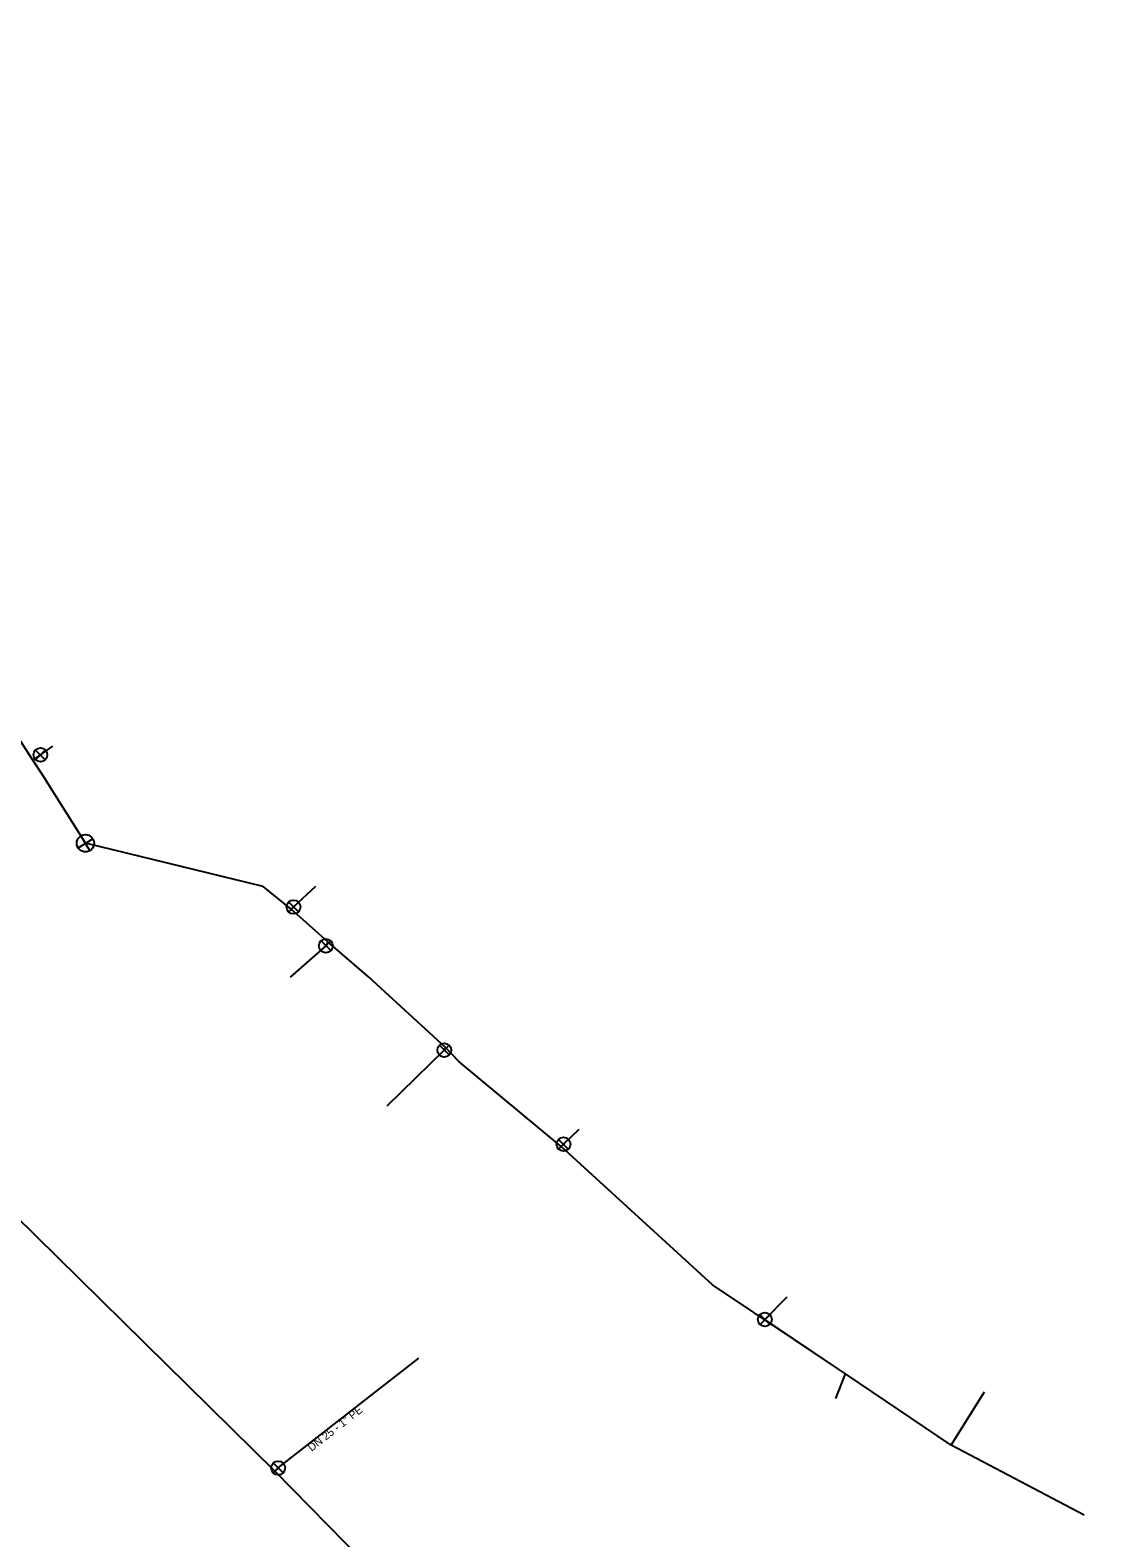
# Model space of a CAD drawing. Extents: x -484785 to -484462, y -1128039 to -1127627.
# Drawn here: x -484646.3 to -484583.5, y -1127805.6 to -1127718.2 of the extents above; entities that cross this region are included whole.
import ezdxf

# ---------------------------------------------------------------- set-up
doc = ezdxf.new("R2010")
doc.units = 0
for name, color, linetype in [('_pripojka_prevzato_z_dokumentace_', 7, 'Continuous'), ('_pripojka_priblizne_', 7, 'Continuous'), ('_voda_smvak_prevzato_z_dokumentace_', 7, 'Continuous'), ('Default', 7, 'Continuous'), ('MoLevel 27', 7, 'Continuous'), ('MoLevel 53', 7, 'Continuous'), ('MoLevel 55', 7, 'Continuous')]:
    doc.layers.add(name, color=color, linetype=linetype)

# ---------------------------------------------------------------- blocks, each defined once
blk = doc.blocks.new('_uzaver_')
at = {"layer": 'Default'}
for p, q in [((-0.000035, -0.000035), (0.000035, 0.000035)), ((0.000035, -0.000035), (-0.000035, 0.000035))]:
    blk.add_line(p, q, dxfattribs=at)
for radius in [0.00005, 0.0000025]:
    blk.add_circle((0, 0), radius, dxfattribs=at)
blk = doc.blocks.new('_uzaver_pripojka_')
at = {"layer": 'Default'}
for p, q in [((-0.000035, -0.000035), (0.000035, 0.000035)), ((0.000035, -0.000035), (-0.000035, 0.000035))]:
    blk.add_line(p, q, dxfattribs=at)
for radius in [0.00005, 0.0000025]:
    blk.add_circle((0, 0), radius, dxfattribs=at)

msp = doc.modelspace()

# ---------------------------------------------------------------- linework, layer by layer
at = {"layer": '_pripojka_prevzato_z_dokumentace_'}
for points in [[(-484646.121, -1127760.523), (-484645.69, -1127760.22), (-484644.967, -1127759.711)], [(-484631.161, -1127769.165), (-484631.03, -1127769.03), (-484629.732, -1127767.818)], [(-484629.046, -1127771.058), (-484629.16, -1127771.28), (-484631.218, -1127773.099)], [(-484622.225, -1127777.17), (-484622.3, -1127777.32), (-484625.631, -1127780.569)], [(-484615.535, -1127782.894), (-484615.4, -1127782.77), (-484614.496, -1127781.89)], [(-484599.525, -1127795.757), (-484603.738, -1127792.924), (-484602.446, -1127791.615)], [(-484632.109, -1127801.7), (-484631.92, -1127801.52), (-484623.781, -1127795.156)], [(-484592.952, -1127800.204), (-484592.84, -1127800.01), (-484591.02, -1127797.109)]]:
    msp.add_lwpolyline(points, dxfattribs=at)
at = {"layer": '_pripojka_priblizne_'}
msp.add_line((-484599.635, -1127797.492), (-484599.059, -1127796.076), dxfattribs=at)
at = {"layer": '_voda_smvak_prevzato_z_dokumentace_'}
for points in [[(-484643.08, -1127765.34), (-484645.558, -1127761.377), (-484646.121, -1127760.523), (-484650.612, -1127753.602), (-484650.955, -1127753.108), (-484652.744, -1127750.288), (-484654.582, -1127747.805), (-484659.496, -1127741.98), (-484663.295, -1127738.246), (-484667.445, -1127734.471), (-484668.218, -1127733.675), (-484673.26, -1127728.099), (-484673.76, -1127727.546), (-484675.038, -1127726.215), (-484681.24, -1127716.168), (-484682.755, -1127712.65), (-484683.576, -1127711.276), (-484684.331, -1127709.732), (-484687.857, -1127701.916), (-484687.921, -1127701.756), (-484691.708, -1127695.751), (-484698.386, -1127690.884), (-484712.097, -1127682.86)], [(-484585.245, -1127804.256), (-484592.952, -1127800.204), (-484599.059, -1127796.076), (-484599.525, -1127795.757), (-484606.767, -1127790.907), (-484615.535, -1127782.894), (-484621.464, -1127777.986), (-484622.225, -1127777.17), (-484626.698, -1127773.076), (-484629.046, -1127771.058), (-484631.161, -1127769.165), (-484632.783, -1127767.838), (-484643.08, -1127765.34)], [(-484648.492, -1127785.585), (-484632.109, -1127801.7), (-484625, -1127808.969), (-484624.296, -1127809.744), (-484623.356, -1127810.97), (-484621.849, -1127813.136), (-484618.11, -1127819.53), (-484617.65, -1127820.12), (-484615.463, -1127823.691), (-484611.477, -1127830.067), (-484610.397, -1127831.791), (-484608.509, -1127835.039), (-484607.695, -1127835.947), (-484607.546, -1127836.169), (-484599.55, -1127849.979), (-484596.391, -1127855.236), (-484593.245, -1127859.963), (-484588.208, -1127868.192), (-484587.397, -1127869.371), (-484583.472, -1127874.589)]]:
    msp.add_lwpolyline(points, dxfattribs=at)

# ---------------------------------------------------------------- block references
at = {"layer": 'MoLevel 27', "xscale": 10000.000000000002, "yscale": 10000, "rotation": -13.64279895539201}
msp.add_blockref('_uzaver_', (-484643.08, -1127765.34), dxfattribs=at)
at = {"layer": 'MoLevel 53', "xscale": 7999.999999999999, "yscale": 7999.999999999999}
for p in [(-484645.69, -1127760.22), (-484631.03, -1127769.03), (-484629.16, -1127771.28), (-484622.3, -1127777.32), (-484615.4, -1127782.77), (-484603.738, -1127792.924), (-484631.92, -1127801.52)]:
    msp.add_blockref('_uzaver_pripojka_', p, dxfattribs=at)

# ---------------------------------------------------------------- texts
at = {"layer": 'MoLevel 55'}
msp.add_text("DN 25 - 1'' PE", height=0.455, rotation=38.02236, dxfattribs=at).set_placement((-484629.986, -1127800.585))

doc.saveas('drawing.dxf')
